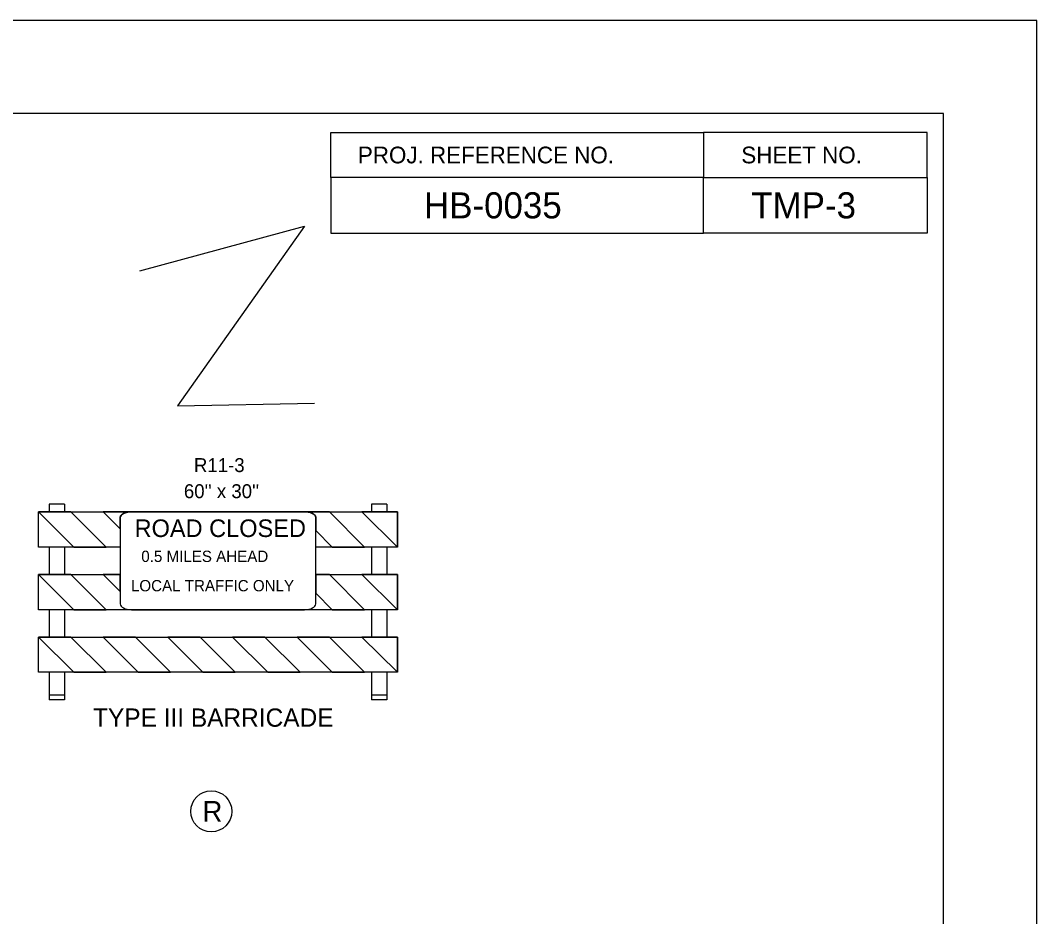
# Model space of a CAD drawing. Extents: x 2157572 to 5059327, y 715220 to 1674494.
# Drawn here: x 2168895 to 2171076, y 729165 to 731089 of the extents above; entities that cross this region are included whole.
import ezdxf

# ---------------------------------------------------------------- set-up
doc = ezdxf.new("R2010")
doc.units = 0
for name, color, linetype in [('Exist Cultural Church Label', 7, 'Continuous'), ('Exist Hydrographic Creek Double Shore Label', 7, 'Continuous'), ('Exist Road Secondary Structure Culvert Number Label', 7, 'Continuous'), ('Exist Road Secondary Type 51 Divided Label', 7, 'Continuous'), ('Level 54', 7, 'Continuous'), ('Map Preparation Border Control Points', 7, 'Continuous'), ('Map Preparation County Base Legend Highway Garage or Maintenance Office', 7, 'Continuous'), ('Map Preparation County Base Legend Lighthouse', 7, 'Continuous'), ('Map Preparation County Inset Control Points', 7, 'Continuous'), ('Map Preparation County North Arrow White Shapes', 7, 'Continuous')]:
    doc.layers.add(name, color=color, linetype=linetype)

msp = doc.modelspace()

# ---------------------------------------------------------------- linework, layer by layer
at = {"layer": 'Exist Cultural Church Label'}
msp.add_circle((2169304.4, 729390.6), 44.1, dxfattribs=at)
at = {"layer": 'Exist Hydrographic Creek Double Shore Label'}
msp.add_line((2169231.7, 730261.4), (2169526, 730266.8), dxfattribs=at)
msp.add_lwpolyline([(2169151.4, 730550.6), (2169504.6, 730647), (2169231.7, 730261.4)], dxfattribs=at)
at = {"layer": 'Exist Road Secondary Type 51 Divided Label'}
msp.add_lwpolyline([(2157571.9, 722288.7), (2171075.9, 722288.7), (2171075.9, 731088.6), (2157571.9, 731088.6)], close=True, dxfattribs=at)
at = {"layer": 'Map Preparation Border Control Points'}
for points in [[(2169108.9, 730021.3), (2169108.9, 729835.8)], [(2169504.4, 730033.5), (2169133.4, 730033.5)], [(2169528.9, 729835.8), (2169528.9, 730021.3)], [(2169133.4, 729823.5), (2169504.4, 729823.5)], [(2169170.5, 729823.5), (2169467.3, 729823.5)]]:
    msp.add_lwpolyline(points, dxfattribs=at)
for centre, major_axis, start_param, end_param in [((2169133.4, 730021.3), (-24.5, 0), 4.712304, 6.283185), ((2169504.4, 730021.3), (24.5, 0), 0, 1.571024), ((2169133.4, 729835.8), (24.5, 0), 3.141593, 4.712389), ((2169504.4, 729835.8), (24.5, 0), 4.712389, 6.283185)]:
    msp.add_ellipse(centre, major_axis=major_axis, ratio=0.5, start_param=start_param, end_param=end_param, dxfattribs=at)
at = {"layer": 'Map Preparation County Base Legend Highway Garage or Maintenance Office'}
msp.add_circle((2169304.4, 729390.6), 44.1, dxfattribs=at)
at = {"layer": 'Map Preparation County Base Legend Lighthouse'}
for p, q in [((2168989.2, 730049.9), (2168956.5, 730049.9)), ((2168956.5, 730049.9), (2168956.5, 730033.5)), ((2168989.2, 730049.9), (2168989.2, 730033.5)), ((2169681.3, 730049.9), (2169648.6, 730049.9)), ((2169648.6, 730049.9), (2169648.6, 730033.5)), ((2169681.3, 730049.9), (2169681.3, 730033.5)), ((2168933.6, 730033.5), (2169704.2, 730033.5)), ((2168933.6, 729958), (2168933.6, 730033.5)), ((2169002.9, 730033.5), (2168933.6, 730033.5)), ((2168933.6, 730033.5), (2169009.1, 729958)), ((2169078.5, 729958), (2169002.9, 730033.5)), ((2169141.6, 730033.5), (2169072.3, 730033.5)), ((2169072.3, 730033.5), (2169108.9, 729996.9)), ((2169133.2, 730033.5), (2169141.6, 730033.5)), ((2169558, 730033.5), (2169488.6, 730033.5)), ((2169633.5, 729958), (2169558, 730033.5)), ((2169704.2, 730033.5), (2169627.3, 730033.5)), ((2169627.3, 730033.5), (2169704.2, 729958)), ((2169704.2, 730033.5), (2169704.2, 729958)), ((2169704.2, 729958), (2169704.2, 730033.5)), ((2169108.9, 729958), (2168933.6, 729958)), ((2168956.5, 729958), (2168956.5, 729899.1)), ((2168989.2, 729958), (2168989.2, 729899.1)), ((2169009.1, 729958), (2169078.5, 729958)), ((2169704.2, 729958), (2169528.9, 729958)), ((2169564.2, 729958), (2169633.5, 729958)), ((2169648.6, 729958), (2169648.6, 729899.1)), ((2169681.3, 729958), (2169681.3, 729899.1)), ((2168933.6, 729823.5), (2168933.6, 729899.1)), ((2169002.9, 729899.1), (2168933.6, 729899.1)), ((2168933.6, 729899.1), (2169009.1, 729823.5)), ((2168933.6, 729899.1), (2169108.9, 729899.1)), ((2169078.5, 729823.5), (2169002.9, 729899.1)), ((2169108.9, 729899.1), (2169072.3, 729899.1)), ((2169072.3, 729899.1), (2169108.9, 729862.4)), ((2169108.9, 729881.3), (2169108.9, 729899.1)), ((2169528.9, 729899.1), (2169704.2, 729899.1)), ((2169633.5, 729823.5), (2169558, 729899.1)), ((2169704.2, 729899.1), (2169627.3, 729899.1)), ((2169627.3, 729899.1), (2169704.2, 729823.5)), ((2169704.2, 729899.1), (2169704.2, 729823.5)), ((2169704.2, 729823.5), (2169704.2, 729899.1)), ((2169108.9, 729862.4), (2169108.9, 729881.3)), ((2169528.9, 729858.8), (2169564.2, 729823.5)), ((2169704.2, 729823.5), (2168933.6, 729823.5)), ((2168956.5, 729823.5), (2168956.5, 729764.6)), ((2168989.2, 729823.5), (2168989.2, 729764.6)), ((2169009.1, 729823.5), (2169078.5, 729823.5)), ((2169564.2, 729823.5), (2169633.5, 729823.5)), ((2169648.6, 729823.5), (2169648.6, 729764.6)), ((2169681.3, 729823.5), (2169681.3, 729764.6)), ((2169002.9, 729764.6), (2168933.6, 729764.6)), ((2168933.6, 729764.6), (2169009.1, 729689.1)), ((2168933.6, 729764.6), (2169704.2, 729764.6)), ((2168933.6, 729689.1), (2168933.6, 729764.6)), ((2169078.5, 729689.1), (2169002.9, 729764.6)), ((2169141.6, 729764.6), (2169072.3, 729764.6)), ((2169072.3, 729764.6), (2169147.8, 729689.1)), ((2169217.2, 729689.1), (2169141.6, 729764.6)), ((2169280.3, 729764.6), (2169210.9, 729764.6)), ((2169210.9, 729764.6), (2169286.5, 729689.1)), ((2169355.8, 729689.1), (2169280.3, 729764.6)), ((2169419.3, 729764.6), (2169350, 729764.6)), ((2169350, 729764.6), (2169425.5, 729689.1)), ((2169494.9, 729689.1), (2169419.3, 729764.6)), ((2169558, 729764.6), (2169488.6, 729764.6)), ((2169488.6, 729764.6), (2169564.2, 729689.1)), ((2169633.5, 729689.1), (2169558, 729764.6)), ((2169704.2, 729764.6), (2169627.3, 729764.6)), ((2169627.3, 729764.6), (2169704.2, 729689.1)), ((2169704.2, 729689.1), (2169704.2, 729764.6)), ((2169704.2, 729764.6), (2169704.2, 729689.1)), ((2169704.2, 729689.1), (2168933.6, 729689.1)), ((2168956.5, 729689.1), (2168956.5, 729630.2)), ((2168989.2, 729689.1), (2168989.2, 729630.2)), ((2169009.1, 729689.1), (2169078.5, 729689.1)), ((2169147.8, 729689.1), (2169217.2, 729689.1)), ((2169286.5, 729689.1), (2169355.8, 729689.1)), ((2169425.5, 729689.1), (2169494.9, 729689.1)), ((2169564.2, 729689.1), (2169633.5, 729689.1)), ((2169648.6, 729689.1), (2169648.6, 729630.2)), ((2169681.3, 729689.1), (2169681.3, 729630.2)), ((2168989.2, 729640), (2168956.5, 729640)), ((2168989.2, 729630.2), (2168956.5, 729630.2)), ((2169681.3, 729640), (2169648.6, 729640)), ((2169681.3, 729630.2), (2169648.6, 729630.2))]:
    msp.add_line(p, q, dxfattribs=at)
for points in [[(2169108.9, 729996.9), (2169108.9, 730021.5), (2169109.9, 730024.7), (2169112.5, 730027.6), (2169116.1, 730029.9), (2169122.2, 730032.1), (2169128, 730033.2), (2169133.2, 730033.5)], [(2169488.6, 730033.5), (2169507.6, 730033.4), (2169512.3, 730032.9), (2169516.5, 730031.9), (2169519.6, 730030.9), (2169522.5, 730029.5), (2169524.9, 730028), (2169526.8, 730026.2), (2169527.9, 730024.8), (2169528.9, 730021.3), (2169528.9, 729993.3), (2169564.2, 729958)], [(2169558, 729899.1), (2169528.9, 729899.1), (2169528.9, 729858.8)]]:
    msp.add_lwpolyline(points, dxfattribs=at)
at = {"layer": 'Map Preparation County Inset Control Points'}
msp.add_lwpolyline([(2169170.5, 730033.5), (2169467.3, 730033.5)], dxfattribs=at)
at = {"layer": 'Map Preparation County North Arrow White Shapes'}
msp.add_line((2170361.1, 730751.5), (2170841.1, 730751.5), dxfattribs=at)
for points in [[(2170875.9, 730888.7), (2158875.9, 730888.7), (2158875.9, 722488.7), (2170875.9, 722488.7)], [(2169561.1, 730847.5), (2170361.1, 730847.5), (2170361.1, 730751.5), (2169561.1, 730751.5)], [(2170361.1, 730751.5), (2170841.1, 730751.5), (2170841.1, 730847.5), (2170361.1, 730847.5)], [(2170361.1, 730751.5), (2169561.1, 730751.5), (2169561.1, 730631.5), (2170361.1, 730631.5)], [(2170361.1, 730751.5), (2170841.1, 730751.5), (2170841.1, 730631.5), (2170361.1, 730631.5)]]:
    msp.add_lwpolyline(points, close=True, dxfattribs=at)

# ---------------------------------------------------------------- texts
at = {"layer": 'Exist Cultural Church Label'}
msp.add_text('R', height=44.3, dxfattribs=at).set_placement((2169285.4, 729368.4))
at = {"layer": 'Exist Road Secondary Structure Culvert Number Label'}
for s, p in [('R11-3', (2169267.2, 730118.9)), ("60'' x 30''", (2169245.6, 730062.9))]:
    msp.add_text(s, height=29.88, dxfattribs=at).set_placement(p)
at = {"layer": 'Level 54'}
for s, height, p in [('ROAD CLOSED', 37.785, (2169139.8, 729979.5)), ('0.5 MILES AHEAD', 24.287, (2169154.2, 729925.9)), ('LOCAL TRAFFIC ONLY', 24.287, (2169132, 729862.9))]:
    msp.add_text(s, height=height, dxfattribs=at).set_placement(p)
at = {"layer": 'Map Preparation County Base Legend Lighthouse'}
msp.add_text('TYPE III BARRICADE', height=39.25, dxfattribs=at).set_placement((2169050.6, 729572.2))
at = {"layer": 'Map Preparation County North Arrow White Shapes'}
for s, height, p in [('PROJ. REFERENCE NO.', 35.909, (2169619.1, 730781.6)), ('SHEET NO.', 35.91, (2170442, 730781.6))]:
    msp.add_text(s, height=height, rotation=0.0006, dxfattribs=at).set_placement(p)
for s, p in [('HB-0035', (2169761, 730663.5)), ('   TMP-3  ', (2170401, 730663.5))]:
    msp.add_text(s, height=56, dxfattribs=at).set_placement(p)

doc.saveas('drawing.dxf')
